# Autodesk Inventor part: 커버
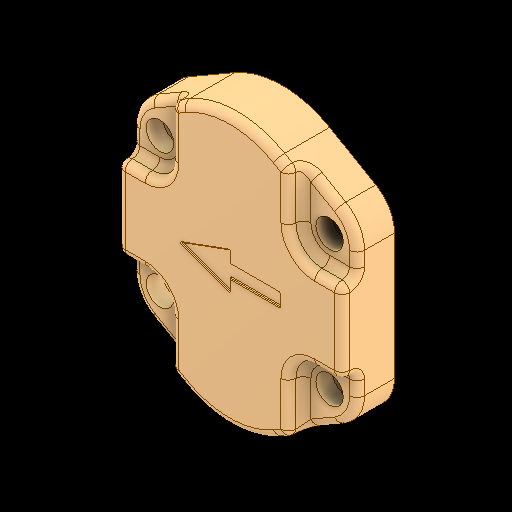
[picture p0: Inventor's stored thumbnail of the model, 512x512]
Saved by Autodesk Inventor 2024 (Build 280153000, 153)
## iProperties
Created: 2025-10
Part Number: 커버
Material: 알루미늄 6061
Document SubType Name: Modeling
Designer: EDU03
Density: 2.7 g/cm^3
Appearance: 기본값
Author: jhkim
Sending System: Autodesk Inventor 2026
Preprocessor: ST-DEVELOPER v20.1
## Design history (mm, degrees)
node "커버1"
node "솔리드1"
node "솔리드2"
